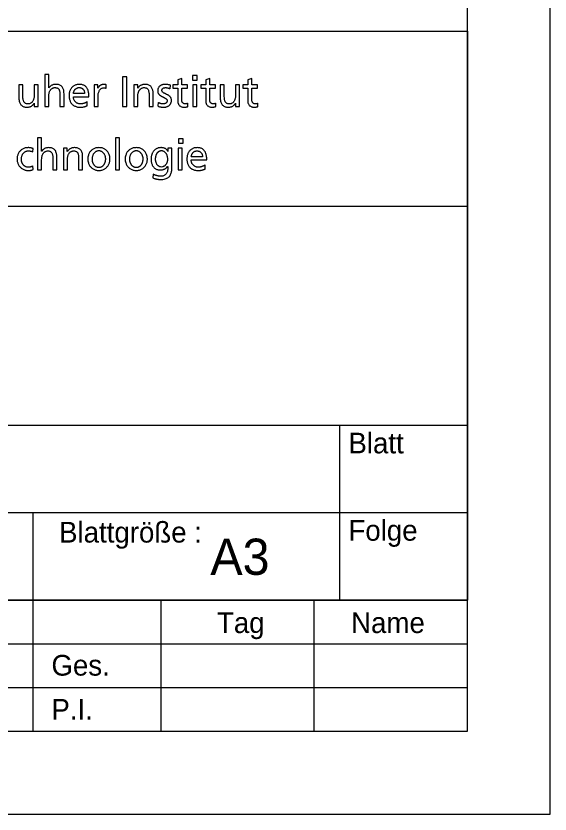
# Model space of a CAD drawing. Extents: x 0 to 105, y 0 to 74.
# Drawn here: x 92.08 to 105, y 0 to 19.29 of the extents above; entities that cross this region are included whole.
import ezdxf

# ---------------------------------------------------------------- set-up
doc = ezdxf.new("R2010")
doc.units = 0
doc.layers.add('90_Plankopf', color=7, linetype='Continuous')

msp = doc.modelspace()

# ---------------------------------------------------------------- linework, layer by layer
at = {"layer": '90_Plankopf'}
for p, q in [((103, 18.92), (103, 25.265)), ((82.001, 18.92), (103, 18.92)), ((103, 18.92), (103, 5.173)), ((103, 18.92), (103, 5.173)), ((94.264, 17.544), (94.264, 17.63)), ((95.808, 17.532), (95.817, 17.617)), ((93.743, 17.413), (93.471, 17.413)), ((93.471, 17.34), (93.847, 17.34)), ((93.806, 17.121), (93.806, 17.218)), ((95.518, 17.202), (95.513, 17.115)), ((96.241, 17.101), (96.241, 17.184)), ((96.917, 17.101), (96.917, 17.184)), ((97.936, 17.101), (97.936, 17.184)), ((92.488, 16.007), (92.496, 16.087)), ((96.593, 15.883), (96.321, 15.883)), ((92.5, 15.578), (92.493, 15.665)), ((96.321, 15.811), (96.697, 15.811)), ((96.656, 15.591), (96.656, 15.688)), ((95.399, 15.466), (95.389, 15.376)), ((82.001, 14.69), (103, 14.69)), ((82.001, 9.402), (103, 9.402)), ((99.912, 5.173), (99.912, 9.402)), ((82.001, 7.288), (103, 7.288)), ((82.001, 5.173), (103, 5.173)), ((82.001, 5.173), (103, 5.173)), ((82.001, 5.173), (103, 5.173)), ((82.001, 5.173), (103, 5.173)), ((95.588, 5.173), (95.588, 2)), ((99.294, 2), (99.294, 5.173)), ((103, 2), (103, 5.173)), ((82.001, 4.115), (92.5, 4.115)), ((92.5, 4.115), (103, 4.115)), ((92.5, 2), (92.5, 4.115)), ((82.001, 3.058), (92.5, 3.058)), ((92.5, 3.058), (103, 3.058)), ((82.001, 2), (103, 2)), ((82.001, 2), (103, 2)), ((92.5, 2), (92.5, 2))]:
    msp.add_line(p, q, dxfattribs=at)
for points in [[(0, 0), (105, 0), (105, 74.25), (0, 74.25)], [(2, 2), (103, 2), (103, 72.25), (2, 72.25)]]:
    msp.add_lwpolyline(points, close=True, dxfattribs=at)
for points in [[(92.878, 17.55), (92.876, 17.55), (92.876, 17.873), (92.779, 17.873), (92.779, 17.099), (92.876, 17.099), (92.876, 17.342)], [(94.662, 17.099), (94.765, 17.099), (94.765, 17.819), (94.662, 17.819), (94.662, 17.099)], [(96.093, 17.259), (96.093, 17.547), (96.232, 17.547), (96.232, 17.625), (96.093, 17.625), (96.093, 17.778), (95.996, 17.747), (95.996, 17.625), (95.877, 17.625), (95.877, 17.547), (95.996, 17.547), (95.996, 17.239)], [(96.464, 17.743), (96.464, 17.852), (96.354, 17.852), (96.354, 17.743), (96.464, 17.743)], [(96.769, 17.259), (96.769, 17.547), (96.908, 17.547), (96.908, 17.625), (96.769, 17.625), (96.769, 17.778), (96.672, 17.747), (96.672, 17.625), (96.553, 17.625), (96.553, 17.547), (96.672, 17.547), (96.672, 17.239)], [(97.789, 17.259), (97.789, 17.547), (97.928, 17.547), (97.928, 17.625), (97.789, 17.625), (97.789, 17.778), (97.692, 17.747), (97.692, 17.625), (97.573, 17.625), (97.573, 17.547), (97.692, 17.547), (97.692, 17.239)], [(92.251, 17.353), (92.251, 17.625), (92.154, 17.625), (92.154, 17.313)], [(92.524, 17.182), (92.526, 17.182), (92.526, 17.099), (92.62, 17.099), (92.62, 17.625), (92.523, 17.625), (92.523, 17.382)], [(94.063, 17.544), (94.061, 17.544), (94.061, 17.625), (93.97, 17.625), (93.97, 17.099), (94.067, 17.099), (94.067, 17.338)], [(95.029, 17.542), (95.027, 17.542), (95.027, 17.625), (94.933, 17.625), (94.933, 17.099), (95.03, 17.099), (95.03, 17.342)], [(96.36, 17.625), (96.36, 17.099), (96.457, 17.099), (96.457, 17.625), (96.36, 17.625)], [(97.121, 17.353), (97.121, 17.625), (97.024, 17.625), (97.024, 17.313)], [(97.393, 17.182), (97.395, 17.182), (97.395, 17.099), (97.489, 17.099), (97.489, 17.625), (97.392, 17.625), (97.392, 17.382)], [(93.147, 17.371), (93.147, 17.099), (93.244, 17.099), (93.244, 17.412)], [(95.302, 17.371), (95.302, 17.099), (95.399, 17.099), (95.399, 17.412)], [(92.705, 16.02), (92.703, 16.02), (92.703, 16.343), (92.606, 16.343), (92.606, 15.569), (92.703, 15.569), (92.703, 15.813)], [(94.491, 15.569), (94.588, 15.569), (94.588, 16.343), (94.491, 16.343), (94.491, 15.569)], [(96.124, 16.213), (96.124, 16.322), (96.014, 16.322), (96.014, 16.213), (96.124, 16.213)], [(93.326, 16.012), (93.324, 16.012), (93.324, 16.095), (93.23, 16.095), (93.23, 15.569), (93.327, 15.569), (93.327, 15.813)], [(95.849, 15.592), (95.849, 16.095), (95.759, 16.095), (95.759, 16.017), (95.757, 16.017)], [(96.008, 16.095), (96.008, 15.569), (96.105, 15.569), (96.105, 16.095), (96.008, 16.095)], [(92.974, 15.841), (92.974, 15.569), (93.071, 15.569), (93.071, 15.882)], [(93.598, 15.841), (93.598, 15.569), (93.695, 15.569), (93.695, 15.882)], [(95.75, 15.651), (95.752, 15.651), (95.752, 15.599)], [(92.5, 2), (92.5, 7.288)], [(103, 5.173), (82.001, 5.173)], [(103, 2), (103, 4.115)], [(82.001, 2), (103, 2)], [(92.5, 2), (103, 2)]]:
    msp.add_lwpolyline(points, dxfattribs=at)
for points in [[(92.876, 17.342), (92.876, 17.375), (92.879, 17.404), (92.885, 17.43), (92.891, 17.457), (92.901, 17.479), (92.914, 17.499), (92.927, 17.518), (92.944, 17.533), (92.964, 17.543), (92.984, 17.554), (93.008, 17.559), (93.036, 17.559), (93.064, 17.557), (93.086, 17.55), (93.102, 17.535), (93.118, 17.521), (93.13, 17.501), (93.137, 17.473), (93.144, 17.446), (93.147, 17.412), (93.147, 17.371)], [(93.244, 17.412), (93.244, 17.459), (93.237, 17.499), (93.223, 17.533), (93.209, 17.567), (93.187, 17.592), (93.158, 17.61), (93.129, 17.628), (93.092, 17.637), (93.047, 17.637), (93.01, 17.637), (92.977, 17.63), (92.948, 17.615), (92.919, 17.6), (92.896, 17.578), (92.878, 17.55)], [(93.847, 17.34), (93.847, 17.383), (93.843, 17.422), (93.835, 17.458), (93.827, 17.494), (93.814, 17.526), (93.796, 17.552), (93.778, 17.579), (93.755, 17.6), (93.725, 17.615), (93.695, 17.63), (93.658, 17.637), (93.614, 17.637), (93.577, 17.637), (93.543, 17.631), (93.513, 17.618), (93.483, 17.605), (93.457, 17.587), (93.435, 17.563), (93.414, 17.539), (93.397, 17.511), (93.386, 17.479), (93.374, 17.446), (93.368, 17.411), (93.368, 17.371), (93.368, 17.328), (93.373, 17.289), (93.384, 17.255), (93.395, 17.22), (93.412, 17.19), (93.434, 17.165), (93.456, 17.14), (93.485, 17.12), (93.519, 17.107), (93.553, 17.093), (93.594, 17.087), (93.64, 17.087), (93.669, 17.087), (93.693, 17.089), (93.714, 17.092), (93.734, 17.096), (93.751, 17.101), (93.766, 17.106), (93.781, 17.111), (93.794, 17.116), (93.806, 17.121)], [(93.471, 17.413), (93.473, 17.43), (93.477, 17.447), (93.483, 17.464), (93.489, 17.481), (93.497, 17.497), (93.509, 17.511), (93.52, 17.526), (93.534, 17.537), (93.551, 17.546), (93.568, 17.554), (93.589, 17.559), (93.612, 17.559), (93.633, 17.559), (93.652, 17.555), (93.668, 17.548), (93.684, 17.54), (93.698, 17.53), (93.709, 17.516), (93.72, 17.503), (93.729, 17.487), (93.735, 17.47), (93.74, 17.452), (93.743, 17.433), (93.743, 17.413)], [(94.264, 17.63), (94.258, 17.632), (94.251, 17.633), (94.245, 17.634), (94.239, 17.635), (94.232, 17.636), (94.225, 17.636), (94.218, 17.637), (94.21, 17.637), (94.201, 17.637), (94.182, 17.637), (94.164, 17.633), (94.146, 17.625), (94.128, 17.617), (94.112, 17.606), (94.098, 17.592), (94.084, 17.578), (94.072, 17.562), (94.063, 17.544)], [(95.399, 17.412), (95.399, 17.459), (95.392, 17.499), (95.378, 17.533), (95.364, 17.567), (95.342, 17.592), (95.313, 17.61), (95.284, 17.628), (95.247, 17.637), (95.201, 17.637), (95.177, 17.637), (95.153, 17.634), (95.131, 17.626), (95.108, 17.618), (95.088, 17.607), (95.07, 17.593), (95.053, 17.579), (95.039, 17.562), (95.029, 17.542)], [(95.03, 17.342), (95.03, 17.375), (95.033, 17.404), (95.04, 17.43), (95.046, 17.457), (95.056, 17.479), (95.069, 17.499), (95.082, 17.518), (95.098, 17.533), (95.119, 17.543), (95.139, 17.554), (95.163, 17.559), (95.19, 17.559), (95.218, 17.557), (95.24, 17.55), (95.257, 17.535), (95.273, 17.521), (95.285, 17.501), (95.291, 17.473), (95.299, 17.446), (95.302, 17.412), (95.302, 17.371)], [(95.817, 17.617), (95.798, 17.623), (95.778, 17.628), (95.759, 17.631), (95.739, 17.635), (95.718, 17.637), (95.696, 17.637), (95.67, 17.637), (95.645, 17.634), (95.623, 17.628), (95.6, 17.621), (95.581, 17.611), (95.564, 17.598), (95.547, 17.584), (95.534, 17.567), (95.525, 17.547), (95.515, 17.527), (95.51, 17.503), (95.51, 17.476), (95.51, 17.455), (95.515, 17.436), (95.523, 17.421), (95.531, 17.406), (95.542, 17.392), (95.555, 17.381), (95.569, 17.37), (95.584, 17.36), (95.6, 17.351), (95.616, 17.343), (95.632, 17.334), (95.648, 17.327), (95.665, 17.319), (95.679, 17.311), (95.693, 17.303), (95.706, 17.295), (95.717, 17.286), (95.726, 17.276), (95.734, 17.266), (95.738, 17.254), (95.738, 17.24), (95.738, 17.226), (95.735, 17.214), (95.729, 17.205), (95.723, 17.195), (95.715, 17.187), (95.705, 17.181), (95.695, 17.175), (95.685, 17.171), (95.673, 17.169), (95.662, 17.166), (95.65, 17.165), (95.639, 17.165), (95.629, 17.165), (95.618, 17.166), (95.604, 17.169), (95.59, 17.172), (95.575, 17.176), (95.56, 17.182), (95.545, 17.187), (95.531, 17.194), (95.518, 17.202)], [(95.513, 17.115), (95.536, 17.104), (95.559, 17.096), (95.584, 17.092), (95.608, 17.088), (95.633, 17.086), (95.658, 17.087), (95.681, 17.087), (95.704, 17.09), (95.726, 17.096), (95.748, 17.103), (95.767, 17.113), (95.785, 17.126), (95.802, 17.14), (95.816, 17.157), (95.826, 17.178), (95.836, 17.198), (95.841, 17.223), (95.841, 17.251), (95.841, 17.275), (95.837, 17.295), (95.829, 17.311), (95.82, 17.328), (95.81, 17.342), (95.796, 17.354), (95.783, 17.366), (95.768, 17.375), (95.752, 17.384), (95.735, 17.392), (95.719, 17.4), (95.703, 17.407), (95.687, 17.414), (95.672, 17.421), (95.659, 17.429), (95.645, 17.437), (95.634, 17.446), (95.626, 17.457), (95.618, 17.467), (95.613, 17.48), (95.613, 17.495), (95.613, 17.51), (95.618, 17.522), (95.626, 17.531), (95.635, 17.541), (95.646, 17.548), (95.66, 17.552), (95.674, 17.557), (95.689, 17.559), (95.706, 17.559), (95.712, 17.559), (95.72, 17.558), (95.729, 17.557), (95.738, 17.555), (95.747, 17.553), (95.758, 17.551), (95.768, 17.548), (95.777, 17.545), (95.786, 17.542), (95.795, 17.539), (95.803, 17.536), (95.808, 17.532)], [(92.523, 17.382), (92.523, 17.35), (92.52, 17.32), (92.513, 17.294), (92.507, 17.267), (92.497, 17.245), (92.484, 17.225), (92.471, 17.206), (92.454, 17.191), (92.434, 17.181), (92.414, 17.17), (92.39, 17.165), (92.363, 17.165), (92.335, 17.167), (92.312, 17.175), (92.296, 17.189), (92.28, 17.203), (92.268, 17.223), (92.261, 17.251), (92.254, 17.278), (92.251, 17.312), (92.251, 17.353)], [(94.067, 17.338), (94.068, 17.383), (94.074, 17.421), (94.085, 17.453), (94.097, 17.485), (94.114, 17.509), (94.135, 17.527), (94.156, 17.544), (94.182, 17.553), (94.211, 17.553), (94.219, 17.553), (94.228, 17.552), (94.237, 17.551), (94.247, 17.55), (94.256, 17.547), (94.264, 17.544)], [(97.392, 17.382), (97.392, 17.35), (97.389, 17.32), (97.383, 17.294), (97.377, 17.267), (97.367, 17.245), (97.354, 17.225), (97.341, 17.206), (97.324, 17.191), (97.304, 17.181), (97.284, 17.17), (97.26, 17.165), (97.232, 17.165), (97.204, 17.167), (97.182, 17.175), (97.166, 17.189), (97.15, 17.203), (97.138, 17.223), (97.131, 17.251), (97.124, 17.278), (97.121, 17.312), (97.121, 17.353)], [(92.154, 17.313), (92.154, 17.265), (92.161, 17.225), (92.175, 17.191), (92.189, 17.157), (92.211, 17.132), (92.24, 17.114), (92.269, 17.096), (92.306, 17.087), (92.351, 17.087), (92.376, 17.087), (92.4, 17.091), (92.422, 17.098), (92.445, 17.106), (92.465, 17.117), (92.482, 17.131), (92.5, 17.145), (92.514, 17.163), (92.524, 17.182)], [(93.806, 17.218), (93.8, 17.213), (93.792, 17.207), (93.78, 17.201), (93.768, 17.195), (93.755, 17.189), (93.74, 17.184), (93.725, 17.178), (93.71, 17.174), (93.693, 17.17), (93.677, 17.167), (93.66, 17.165), (93.644, 17.165), (93.621, 17.165), (93.599, 17.169), (93.578, 17.178), (93.558, 17.186), (93.539, 17.198), (93.523, 17.214), (93.507, 17.229), (93.494, 17.248), (93.485, 17.269), (93.476, 17.291), (93.471, 17.314), (93.471, 17.34)], [(95.996, 17.239), (95.996, 17.204), (96.003, 17.175), (96.016, 17.153), (96.029, 17.13), (96.048, 17.114), (96.072, 17.103), (96.096, 17.092), (96.125, 17.087), (96.158, 17.087), (96.174, 17.087), (96.189, 17.088), (96.203, 17.092), (96.217, 17.094), (96.23, 17.098), (96.241, 17.101)], [(96.241, 17.184), (96.233, 17.179), (96.224, 17.174), (96.213, 17.171), (96.202, 17.167), (96.19, 17.165), (96.175, 17.165), (96.16, 17.165), (96.146, 17.169), (96.134, 17.176), (96.122, 17.183), (96.112, 17.194), (96.104, 17.207), (96.097, 17.221), (96.093, 17.239), (96.093, 17.259)], [(96.672, 17.239), (96.672, 17.204), (96.679, 17.175), (96.692, 17.153), (96.705, 17.13), (96.724, 17.114), (96.748, 17.103), (96.772, 17.092), (96.801, 17.087), (96.834, 17.087), (96.85, 17.087), (96.865, 17.088), (96.879, 17.092), (96.893, 17.094), (96.906, 17.098), (96.917, 17.101)], [(96.917, 17.184), (96.909, 17.179), (96.9, 17.174), (96.889, 17.171), (96.878, 17.167), (96.866, 17.165), (96.851, 17.165), (96.836, 17.165), (96.822, 17.169), (96.81, 17.176), (96.798, 17.183), (96.788, 17.194), (96.78, 17.207), (96.773, 17.221), (96.769, 17.239), (96.769, 17.259)], [(97.024, 17.313), (97.024, 17.265), (97.031, 17.225), (97.045, 17.191), (97.059, 17.157), (97.08, 17.132), (97.11, 17.114), (97.139, 17.096), (97.176, 17.087), (97.221, 17.087), (97.246, 17.087), (97.269, 17.091), (97.292, 17.098), (97.314, 17.106), (97.335, 17.117), (97.352, 17.131), (97.37, 17.145), (97.384, 17.163), (97.393, 17.182)], [(97.692, 17.239), (97.692, 17.204), (97.698, 17.175), (97.711, 17.153), (97.725, 17.13), (97.743, 17.114), (97.767, 17.103), (97.791, 17.092), (97.82, 17.087), (97.854, 17.087), (97.869, 17.087), (97.884, 17.088), (97.898, 17.092), (97.913, 17.094), (97.925, 17.098), (97.936, 17.101)], [(97.936, 17.184), (97.929, 17.179), (97.92, 17.174), (97.909, 17.171), (97.898, 17.167), (97.885, 17.165), (97.87, 17.165), (97.855, 17.165), (97.842, 17.169), (97.829, 17.176), (97.817, 17.183), (97.807, 17.194), (97.8, 17.207), (97.793, 17.221), (97.789, 17.239), (97.789, 17.259)], [(92.496, 16.087), (92.487, 16.091), (92.476, 16.094), (92.462, 16.098), (92.449, 16.101), (92.435, 16.103), (92.42, 16.105), (92.406, 16.107), (92.392, 16.108), (92.379, 16.108), (92.338, 16.107), (92.302, 16.101), (92.269, 16.087), (92.236, 16.074), (92.208, 16.055), (92.184, 16.03), (92.161, 16.005), (92.142, 15.976), (92.13, 15.943), (92.117, 15.909), (92.111, 15.872), (92.11, 15.832), (92.111, 15.794), (92.117, 15.759), (92.13, 15.726), (92.143, 15.692), (92.161, 15.663), (92.185, 15.638), (92.209, 15.613), (92.237, 15.593), (92.27, 15.579), (92.303, 15.564), (92.339, 15.557), (92.379, 15.557), (92.391, 15.557), (92.403, 15.557), (92.417, 15.558), (92.431, 15.559), (92.445, 15.561), (92.459, 15.564), (92.473, 15.568), (92.487, 15.572), (92.5, 15.578)], [(92.493, 15.665), (92.483, 15.659), (92.472, 15.653), (92.46, 15.649), (92.448, 15.644), (92.436, 15.641), (92.424, 15.639), (92.412, 15.636), (92.4, 15.635), (92.389, 15.635), (92.364, 15.635), (92.342, 15.639), (92.323, 15.647), (92.304, 15.654), (92.287, 15.664), (92.273, 15.677), (92.259, 15.691), (92.248, 15.705), (92.239, 15.722), (92.231, 15.739), (92.224, 15.757), (92.22, 15.776), (92.216, 15.794), (92.214, 15.813), (92.214, 15.832), (92.214, 15.857), (92.217, 15.882), (92.225, 15.905), (92.232, 15.929), (92.243, 15.95), (92.258, 15.968), (92.272, 15.987), (92.29, 16.002), (92.311, 16.013), (92.332, 16.023), (92.356, 16.029), (92.383, 16.029), (92.399, 16.029), (92.415, 16.028), (92.433, 16.024), (92.451, 16.02), (92.469, 16.014), (92.488, 16.007)], [(92.703, 15.813), (92.703, 15.845), (92.706, 15.874), (92.712, 15.9), (92.719, 15.927), (92.728, 15.95), (92.741, 15.969), (92.754, 15.988), (92.771, 16.003), (92.791, 16.013), (92.811, 16.024), (92.835, 16.029), (92.863, 16.029), (92.891, 16.028), (92.913, 16.02), (92.929, 16.005), (92.946, 15.991), (92.957, 15.971), (92.964, 15.944), (92.971, 15.916), (92.974, 15.882), (92.974, 15.841)], [(93.071, 15.882), (93.071, 15.929), (93.064, 15.969), (93.05, 16.003), (93.036, 16.037), (93.015, 16.063), (92.986, 16.08), (92.957, 16.098), (92.919, 16.107), (92.874, 16.108), (92.837, 16.107), (92.804, 16.1), (92.775, 16.085), (92.746, 16.07), (92.723, 16.048), (92.705, 16.02)], [(93.695, 15.882), (93.696, 15.929), (93.689, 15.969), (93.675, 16.003), (93.661, 16.037), (93.639, 16.063), (93.61, 16.08), (93.581, 16.098), (93.544, 16.107), (93.498, 16.108), (93.474, 16.108), (93.45, 16.104), (93.428, 16.096), (93.405, 16.088), (93.385, 16.078), (93.367, 16.063), (93.35, 16.049), (93.336, 16.032), (93.326, 16.012)], [(93.327, 15.813), (93.327, 15.845), (93.33, 15.874), (93.337, 15.9), (93.343, 15.927), (93.353, 15.95), (93.366, 15.969), (93.379, 15.988), (93.395, 16.003), (93.415, 16.013), (93.436, 16.024), (93.459, 16.029), (93.487, 16.029), (93.515, 16.028), (93.537, 16.02), (93.554, 16.005), (93.57, 15.991), (93.581, 15.971), (93.588, 15.944), (93.595, 15.916), (93.599, 15.882), (93.598, 15.841)], [(94.349, 15.895), (94.346, 15.912), (94.341, 15.928), (94.336, 15.943), (94.323, 15.976), (94.305, 16.005), (94.281, 16.03), (94.258, 16.055), (94.229, 16.074), (94.197, 16.087), (94.164, 16.101), (94.128, 16.107), (94.088, 16.108), (94.047, 16.107), (94.011, 16.101), (93.978, 16.087), (93.945, 16.074), (93.917, 16.055), (93.893, 16.03), (93.87, 16.005), (93.851, 15.976), (93.839, 15.943), (93.826, 15.909), (93.82, 15.872), (93.819, 15.832)], [(93.922, 15.832), (93.922, 15.857), (93.926, 15.882), (93.934, 15.905), (93.941, 15.929), (93.952, 15.95), (93.966, 15.968), (93.98, 15.987), (93.997, 16.002), (94.018, 16.013), (94.038, 16.023), (94.061, 16.029), (94.088, 16.029), (94.113, 16.029), (94.136, 16.023), (94.157, 16.013), (94.177, 16.002), (94.194, 15.987), (94.208, 15.968), (94.222, 15.95), (94.233, 15.929), (94.24, 15.905), (94.248, 15.882), (94.252, 15.857), (94.252, 15.832), (94.252, 15.813), (94.25, 15.794), (94.245, 15.776), (94.241, 15.757), (94.235, 15.739), (94.226, 15.722), (94.218, 15.705), (94.207, 15.691), (94.194, 15.677), (94.181, 15.664), (94.166, 15.654), (94.148, 15.647), (94.131, 15.639), (94.11, 15.635), (94.088, 15.635), (94.065, 15.635), (94.044, 15.639), (94.026, 15.647), (94.009, 15.654), (93.993, 15.664), (93.98, 15.677), (93.967, 15.691), (93.956, 15.705), (93.948, 15.722), (93.939, 15.739), (93.933, 15.757), (93.929, 15.776), (93.925, 15.794), (93.922, 15.813), (93.922, 15.832)], [(95.254, 15.895), (95.251, 15.912), (95.246, 15.928), (95.241, 15.943), (95.228, 15.976), (95.21, 16.005), (95.186, 16.03), (95.163, 16.055), (95.134, 16.074), (95.102, 16.087), (95.069, 16.101), (95.033, 16.107), (94.993, 16.108), (94.952, 16.107), (94.916, 16.101), (94.883, 16.087), (94.85, 16.074), (94.822, 16.055), (94.798, 16.03), (94.775, 16.005), (94.756, 15.976), (94.744, 15.943), (94.731, 15.909), (94.725, 15.872), (94.724, 15.832)], [(94.828, 15.832), (94.828, 15.857), (94.831, 15.882), (94.839, 15.905), (94.846, 15.929), (94.857, 15.95), (94.871, 15.968), (94.885, 15.987), (94.903, 16.002), (94.923, 16.013), (94.943, 16.023), (94.966, 16.029), (94.993, 16.029), (95.018, 16.029), (95.041, 16.023), (95.062, 16.013), (95.082, 16.002), (95.099, 15.987), (95.113, 15.968), (95.127, 15.95), (95.138, 15.929), (95.145, 15.905), (95.153, 15.882), (95.157, 15.857), (95.157, 15.832), (95.157, 15.813), (95.155, 15.794), (95.15, 15.776), (95.146, 15.757), (95.14, 15.739), (95.132, 15.722), (95.123, 15.705), (95.112, 15.691), (95.099, 15.677), (95.086, 15.664), (95.071, 15.654), (95.053, 15.647), (95.036, 15.639), (95.015, 15.635), (94.993, 15.635), (94.97, 15.635), (94.949, 15.639), (94.931, 15.647), (94.914, 15.654), (94.898, 15.664), (94.885, 15.677), (94.872, 15.691), (94.861, 15.705), (94.853, 15.722), (94.844, 15.739), (94.838, 15.757), (94.834, 15.776), (94.83, 15.794), (94.828, 15.813), (94.828, 15.832)], [(95.757, 16.017), (95.748, 16.036), (95.735, 16.052), (95.72, 16.066), (95.705, 16.079), (95.686, 16.09), (95.664, 16.097), (95.641, 16.104), (95.615, 16.108), (95.584, 16.108), (95.552, 16.107), (95.524, 16.102), (95.498, 16.091), (95.473, 16.081), (95.451, 16.067), (95.432, 16.048), (95.414, 16.03), (95.398, 16.009), (95.386, 15.985), (95.373, 15.961), (95.364, 15.936), (95.358, 15.909), (95.352, 15.882), (95.349, 15.855), (95.349, 15.828), (95.349, 15.794), (95.353, 15.761), (95.363, 15.73), (95.372, 15.699), (95.386, 15.672), (95.405, 15.647), (95.423, 15.623), (95.447, 15.604), (95.475, 15.59), (95.503, 15.577), (95.536, 15.57), (95.574, 15.569), (95.596, 15.569), (95.618, 15.572), (95.64, 15.578), (95.662, 15.584), (95.682, 15.593), (95.701, 15.605), (95.72, 15.617), (95.736, 15.632), (95.75, 15.651)], [(95.598, 15.647), (95.576, 15.648), (95.555, 15.653), (95.537, 15.663), (95.519, 15.672), (95.504, 15.686), (95.491, 15.703), (95.478, 15.72), (95.469, 15.74), (95.462, 15.762), (95.455, 15.785), (95.452, 15.808), (95.452, 15.833), (95.452, 15.851), (95.454, 15.87), (95.458, 15.888), (95.461, 15.906), (95.467, 15.924), (95.475, 15.941), (95.483, 15.958), (95.493, 15.973), (95.504, 15.986), (95.516, 15.999), (95.53, 16.01), (95.546, 16.018), (95.561, 16.025), (95.579, 16.029), (95.598, 16.029), (95.624, 16.029), (95.647, 16.024), (95.666, 16.013), (95.685, 16.002), (95.701, 15.987), (95.714, 15.969), (95.727, 15.95), (95.736, 15.928), (95.743, 15.904), (95.749, 15.879), (95.752, 15.853), (95.752, 15.826), (95.752, 15.801), (95.748, 15.778), (95.741, 15.757), (95.733, 15.735), (95.723, 15.716), (95.709, 15.7), (95.696, 15.684), (95.68, 15.671), (95.661, 15.662), (95.642, 15.652), (95.621, 15.648), (95.598, 15.647)], [(96.697, 15.811), (96.697, 15.853), (96.693, 15.892), (96.685, 15.928), (96.677, 15.964), (96.664, 15.996), (96.646, 16.023), (96.628, 16.049), (96.605, 16.07), (96.575, 16.085), (96.545, 16.1), (96.508, 16.107), (96.464, 16.108), (96.427, 16.107), (96.393, 16.101), (96.363, 16.088), (96.333, 16.075), (96.307, 16.057), (96.285, 16.033), (96.264, 16.009), (96.247, 15.981), (96.236, 15.949), (96.224, 15.916), (96.218, 15.881), (96.218, 15.841), (96.218, 15.798), (96.223, 15.76), (96.234, 15.725), (96.245, 15.69), (96.262, 15.66), (96.284, 15.635), (96.306, 15.61), (96.335, 15.591), (96.369, 15.577), (96.403, 15.564), (96.444, 15.557), (96.49, 15.557), (96.519, 15.557), (96.543, 15.559), (96.564, 15.563), (96.584, 15.566), (96.601, 15.571), (96.616, 15.576), (96.631, 15.581), (96.644, 15.586), (96.656, 15.591)], [(96.321, 15.883), (96.323, 15.9), (96.327, 15.917), (96.333, 15.934), (96.339, 15.951), (96.348, 15.967), (96.359, 15.982), (96.37, 15.996), (96.384, 16.007), (96.401, 16.016), (96.418, 16.025), (96.439, 16.029), (96.462, 16.029), (96.483, 16.029), (96.502, 16.025), (96.518, 16.018), (96.534, 16.01), (96.548, 16), (96.559, 15.986), (96.57, 15.973), (96.579, 15.957), (96.585, 15.94), (96.59, 15.922), (96.593, 15.903), (96.593, 15.883)], [(93.819, 15.832), (93.82, 15.794), (93.826, 15.759), (93.839, 15.726), (93.852, 15.692), (93.87, 15.663), (93.894, 15.638), (93.918, 15.613), (93.946, 15.593), (93.979, 15.579), (94.011, 15.564), (94.048, 15.557), (94.088, 15.557), (94.127, 15.557), (94.163, 15.564), (94.196, 15.579), (94.229, 15.593), (94.257, 15.613), (94.28, 15.638), (94.304, 15.663), (94.322, 15.692), (94.335, 15.726), (94.348, 15.759), (94.355, 15.794), (94.355, 15.832), (94.355, 15.854), (94.353, 15.875), (94.349, 15.895)], [(94.724, 15.832), (94.725, 15.794), (94.731, 15.759), (94.744, 15.726), (94.757, 15.692), (94.775, 15.663), (94.799, 15.638), (94.823, 15.613), (94.851, 15.593), (94.884, 15.579), (94.916, 15.564), (94.953, 15.557), (94.993, 15.557), (95.032, 15.557), (95.068, 15.564), (95.101, 15.579), (95.134, 15.593), (95.162, 15.613), (95.185, 15.638), (95.209, 15.663), (95.227, 15.692), (95.24, 15.726), (95.253, 15.759), (95.26, 15.794), (95.26, 15.832), (95.26, 15.854), (95.258, 15.875), (95.254, 15.895)], [(96.656, 15.688), (96.65, 15.683), (96.642, 15.677), (96.63, 15.671), (96.619, 15.665), (96.605, 15.66), (96.59, 15.654), (96.576, 15.649), (96.56, 15.644), (96.543, 15.641), (96.527, 15.637), (96.511, 15.635), (96.494, 15.635), (96.471, 15.635), (96.449, 15.639), (96.429, 15.648), (96.408, 15.656), (96.389, 15.668), (96.373, 15.684), (96.357, 15.699), (96.344, 15.718), (96.335, 15.739), (96.326, 15.761), (96.321, 15.784), (96.321, 15.811)], [(95.389, 15.376), (95.417, 15.367), (95.442, 15.359), (95.463, 15.354), (95.484, 15.349), (95.504, 15.345), (95.523, 15.343), (95.541, 15.341), (95.559, 15.34), (95.578, 15.34), (95.64, 15.34), (95.692, 15.35), (95.732, 15.37), (95.772, 15.389), (95.802, 15.418), (95.821, 15.455), (95.84, 15.493), (95.849, 15.538), (95.849, 15.592)], [(95.752, 15.599), (95.752, 15.562), (95.746, 15.53), (95.733, 15.503), (95.72, 15.476), (95.701, 15.455), (95.677, 15.44), (95.652, 15.426), (95.623, 15.419), (95.589, 15.418), (95.571, 15.418), (95.555, 15.419), (95.54, 15.421), (95.525, 15.423), (95.51, 15.426), (95.495, 15.43), (95.481, 15.433), (95.466, 15.438), (95.45, 15.444), (95.435, 15.45), (95.418, 15.458), (95.399, 15.466)]]:
    msp.add_open_spline(points, degree=3, dxfattribs=at)

# ---------------------------------------------------------------- texts
for s, height, p in [('Blatt', 0.5, (100.123, 8.718)), ('Blattgröße :', 0.49998, (93.125, 6.562)), ('Folge', 0.5, (100.123, 6.607)), ('A3   ', 0.875, (96.784, 5.782)), ('Tag', 0.5, (96.943, 4.375)), ('Name', 0.5, (100.188, 4.375)), ('Ges.', 0.5, (92.94, 3.346)), ('P.I.', 0.5, (92.94, 2.281))]:
    msp.add_text(s, height=height, dxfattribs=at).set_placement(p)

doc.saveas('drawing.dxf')
